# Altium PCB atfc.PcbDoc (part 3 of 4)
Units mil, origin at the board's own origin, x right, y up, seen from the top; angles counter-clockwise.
Board outline 6334.43 x 4147 mil, 6 copper layers (Component Side, Ground Plane (GND), GND/Signal, VCCO/Signal, VCCINT/VCCAUX, Bottom Side), stack 60.473 mil thick; 297 components, 274 nets, 1530 pads, 922 vias.
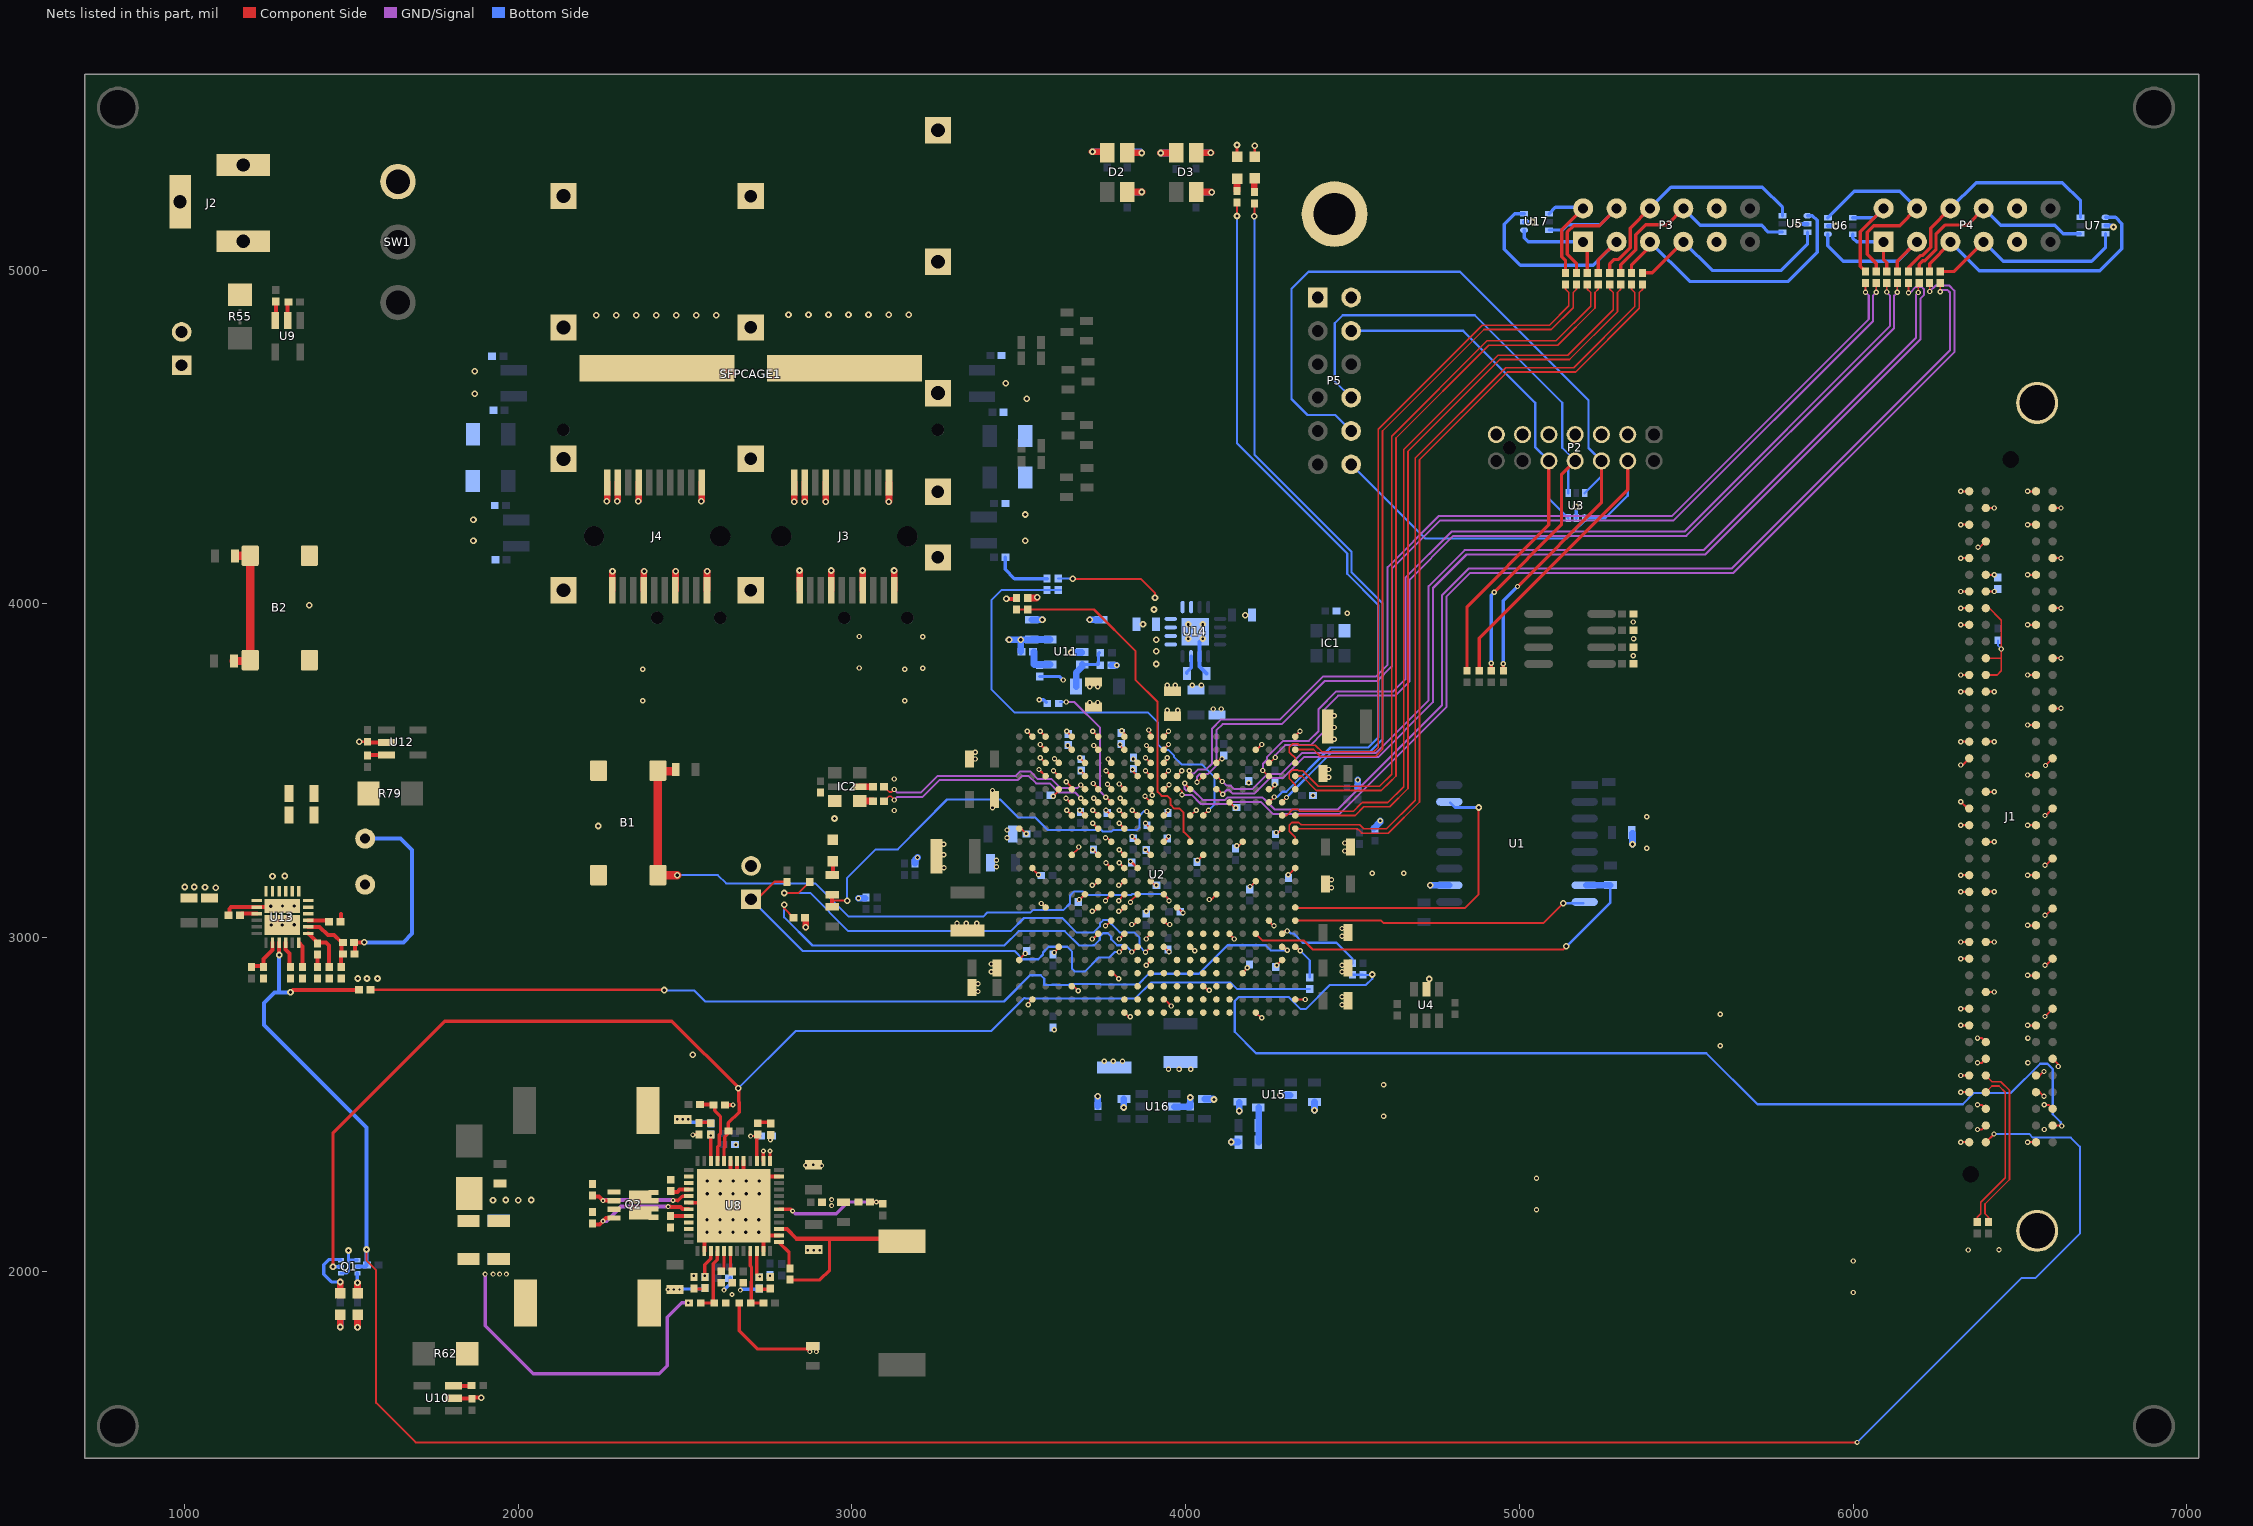
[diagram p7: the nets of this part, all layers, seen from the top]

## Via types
v1: diameter 16, hole 8, Component Side to Bottom Side, tented both sides, 374 vias
v2: diameter 20, hole 10, Component Side to Bottom Side, 243 vias
v3: diameter 16, hole 8, Component Side to Bottom Side, 222 vias
v4: diameter 15, hole 7, Component Side to Bottom Side, 58 vias
v5: diameter 25, hole 10, Component Side to Bottom Side, 20 vias
v6: diameter 19.68, hole 7.87, Component Side to Bottom Side, 4 vias
v7: diameter 20, hole 10, Component Side to Bottom Side, tented both sides, 1 vias

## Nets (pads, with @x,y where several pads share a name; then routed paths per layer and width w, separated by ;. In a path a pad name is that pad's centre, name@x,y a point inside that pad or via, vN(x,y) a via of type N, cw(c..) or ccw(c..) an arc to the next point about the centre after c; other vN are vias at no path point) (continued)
FZ1: U2.AA9 U2.AA10 U2.AA11 U2.AA13 U2.AA14 U2.AA15 U2.AA16 U2.AA17 U2.AB10 U2.AB11 U2.AB12 U2.AB13 U2.AB14 U2.AB15 U2.AB16 U2.AB17 U2.T14 U2.T15 U2.T16 U2.U15 U2.U16 U2.V10 U2.V13 U2.V14 U2.V15 U2.V16 U2.W10 U2.W11 U2.W12 U2.W13 U2.W14 U2.W15 U2.W16 U2.Y10 U2.Y11 U2.Y12 U2.Y13 U2.Y14 U2.Y16 U2.Y17
GBTCLK_N: C4.1 J1.D5 | length 519.3
  Component Side w5: J1.D5@6397.44,2587.2 6415.94,2568.7 6442.39,2568.7 6468.5,2542.59 6468.5,2275.59 6395.01,2202.1 6395.01,2172.45 6405.51,2161.95 C4.1@6405.51,2147.64
GBTCLK_P: C3.1 J1.D4 | length 497.7
  Component Side w5: C3.1@6371.51,2147.64 6371.51,2161.95 6382.01,2172.45 6382.01,2207.48 6455.5,2280.98 6455.5,2537.21 6437.01,2555.7 6415.94,2555.7 J1.D4@6397.44,2537.2
GND: B1.1 B1.2 B2.1 B2.2 C1.1 C2.1 C5.1 C8.1 C9.2 C10.2 C11.2 C12.2 C13.2 C14.2 C15.2 C24.2 C25.2 C26.2 C27.2 C28.2 C29.2 C30.2 C31.2 C32.2 C33.2 C34.2 C35.2 C36.2 C37.2 C38.2 C39.2 C40.2 C41.2 C42.2 C43.2 C44.2 C45.2 C46.2 C47.2 C48.2 C49.1 C50.2 C51.2 C52.2 C53.2 C54.2 C55.2 C56.2 C57.2 C58.2 C59.2 C60.2 C61.2 C62.2 C63.2 C64.2 C65.2 C66.2 C67.2 C68.2 C69.1 C70.1 C71.1 C72.1 C73.1 C74.1 C75.1 C76.1 C77.1 C80.1 C81.1 C82.1 C83.1 C86.1 C88.2 C89.1 C93.1 C95.1 C96.1 C97.1 C98.2 C99.2 C100.2 C101.2 C102.2 C103.2 C107.2 C108.2 C110.2 C111.1 C112.2 C113.2 C114.2 C115.2 C116.2 C117.2 C118.2 C119.1 C120.1 C121.2 C122.1 C123.1 C124.2 C125.1 C126.1 C127.2 C128.1 C129.1 C130.1 Cout1.1 Cout2.1 D1.2 D4.2 D5.2 IC1.3 IC2.3 J1.C1 J1.C4 J1.C5 J1.C8 J1.C9 J1.C12 J1.C13 J1.C16 J1.C17 J1.C20 J1.C21 J1.C24 J1.C25 J1.C28 J1.C29 J1.C32 J1.C33 J1.C34 J1.C36 J1.C38 J1.C40 J1.D2 J1.D3 J1.D6 J1.D7 J1.D10 J1.D13 J1.D16 J1.D19 J1.D22 J1.D25 J1.D28 J1.D35 J1.D37 J1.D39 J1.G1 J1.G4 J1.G5 J1.G8 J1.G11 J1.G14 J1.G17 J1.G20 J1.G23 J1.G26 J1.G29 J1.G32 J1.G35 J1.G38 J1.G40 J1.H3 J1.H6 J1.H9 J1.H12 J1.H15 J1.H18 J1.H21 J1.H24 J1.H27 J1.H30 J1.H33 J1.H36 J1.H39 J2.2 J2.3 J3.1 J3.7 J3.9 J3.10 J3.11 J3.14 J3.17 J3.20 J4.1 J4.7 J4.9 J4.10 J4.11 J4.14 J4.17 J4.20 P1.2 P2.3 P2.5 P2.7 P2.9 P2.11 P2.13 P3.5 P3.11 P4.5 P4.11 P5.1 P5.2 P6.1 pad.2 pad.MH3@6551.18,2121.68 pad.MH3@6551.18,4602 Q1.1 Q1.4 Q2.1 Q2.3 R6.1 R20.1 R24.2 R26.2 R28.2 R30.2 R32.2 R34.2 R48.2 R49.2 R50.2 R51.2 R56.1 R57.1 R58.1 R59.2 R60.1 R63.2 R64.2 R65.1 R67.1 R68.1 R71.1 R73.1 R74.1 R78.1 R82.1 R83.1 Ren2.1 Rf2.1 Rout1.1 Rout2.1 Rout3.1 Rt1.1 SFPCAGE1.1 SFPCAGE1.2 SFPCAGE1.3 SFPCAGE1.4 SFPCAGE1.5 SFPCAGE1.6 SFPCAGE1.7 SFPCAGE1.8 SFPCAGE1.9 SFPCAGE1.10 SFPCAGE1.11 SFPCAGE1.12 SFPCAGE1.13 SFPCAGE1.14 SFPCAGE1.15 SW1.1 U1.10 U2.A2 U2.A3 U2.A5 U2.A7 U2.A9 U2.A11 U2.A12 U2.A22 U2.AA2 U2.AA12 U2.AA22 U2.AB9 U2.AB19 U2.B3 U2.B12 U2.B19 U2.C3 U2.C6 U2.C10 U2.C11 U2.C12 U2.C16 U2.D3 U2.D4 U2.D8 U2.D11 U2.D12 U2.D13 U2.E4 U2.E5 U2.E7 U2.E9 U2.E11 U2.E12 U2.E20 U2.F5 U2.F11 U2.F17 U2.G5 U2.G6 U2.G7 U2.G8 U2.G9 U2.G10 U2.G12 U2.G14 U2.H1 U2.H7 U2.H9 U2.H11 U2.H21 U2.J8 U2.J10 U2.J12 U2.J18 U2.K5 U2.K7 U2.K9 U2.K11 U2.K15 U2.L2 U2.L8 U2.L9 U2.L10 U2.L22 U2.M7 U2.M9 U2.M11 U2.M19 U2.N6 U2.N8 U2.N9 U2.N10 U2.N16 U2.P3 U2.P7 U2.P9 U2.P11 U2.P13 U2.R8 U2.R10 U2.R12 U2.R20 U2.T7 U2.T9 U2.T11 U2.T17 U2.U4 U2.U14 U2.V1 U2.V11 U2.V21 U2.W8 U2.W18 U2.Y5 U2.Y15 U3.2 U4.2 U5.2 U6.2 U7.2 U8.2 U8.11 U8.13 U8.14 U8.17 U8.18 U8.19 U8.30 U8.38 U8.47 U8.49 U9.2 U10.2 U11.2 U12.2 U13.4 U13.4_1 U13.8 U13.9 U13.10 U13.11 U13.12 U13.13 U14.6 U14.17 U15.2 U16.2 U17.2 | length 7405.3
  Component Side w5: U2.E11@3897.09,3444.91 3900,3442 v1(3900,3427) ; U2.E12@3934.69,3444.91 3936.91,3444.91 v1(3950,3458)
  Component Side w6: U2.V1@3501.61,2933.09 3501.61,2934.69 v1(3519.68,2952.76) ; U2.H1@3501.61,3326.8 3506.87,3326.8 v1(3522.64,3311.02) ; v1(3525.24,3618.13) U2.A2@3540.98,3602.39 ; v1(3528,2799.21) 3528,2801.12 3527.56,2801.56 U2.AA2@3540.98,2814.98 ; U2.L2@3540.98,3208.68 3540.98,3207.05 v1(3559.06,3188.98) ; v1(3560.67,3503.96) U2.D3@3580.35,3484.28 ; v1(3564.61,3539.39) U2.C3@3580.35,3523.65 ; v1(3564.61,3578.76) U2.B3@3580.35,3563.02 ; v1(3564.61,3618.13) U2.A3@3580.35,3602.39 ; v1(3566.93,3102.36) 3566.93,3104 U2.P3@3580.35,3090.57 ; v1(3603,3424) 3619.72,3440.72 U2.E4@3619.72,3444.91 ; v1(3603.98,3500.02) U2.D4@3619.72,3484.28 ; v1(3606.3,2955.69) 3606.3,2956.69 U2.U4@3619.72,2970.12 ; v1(3641.72,3417.32) 3653.46,3405.54 U2.F5@3659.09,3405.54 ; v1(3642,3467) 3659.09,3449.91 U2.E5@3659.09,3444.91 ; v1(3643.35,3381.91) U2.G5@3659.09,3366.17 ; v1(3643.35,3618.13) U2.A5@3659.09,3602.39 ; U2.Y5@3659.09,2854.35 3665.33,2854.35 3678,2841.69 v1(3678,2841) ; U2.K5@3659.09,3248.06 3679.61,3268.57 v1(3679.61,3271.61) ; v1@3678,3109.48 U2.N6@3698.46,3129.94 ; v1(3682.72,3381.91) U2.G6@3698.46,3366.17 ; v1(3682.72,3539.39) U2.C6@3698.46,3523.65 ; v1(3720.1,3157.24) 3720.1,3156.42 3722.52,3154 U2.M7@3737.83,3169.31 ; v1(3720.47,2996.06) 3722.06,2996.06 U2.T7@3737.83,3011.83 ; v1(3720.47,3078.73) 3720.47,3076.4 3722.06,3074.8 U2.P7@3737.83,3090.57 ; v1(3722.09,3263.8) U2.K7@3737.83,3248.06 ; v1(3722.09,3342.54) U2.H7@3737.83,3326.8 ; v1(3722.09,3381.91) U2.G7@3737.83,3366.17 ; v1(3722.09,3618.13) U2.A7@3737.83,3602.39 ; v1(3723,3462) 3737.83,3447.17 U2.E7@3737.83,3444.91 ; v1(3759.84,3035.43) 3761.43,3035.43 U2.R8@3777.2,3051.2 ; v1(3759.84,3110.24) 3759.84,3112.58 U2.N8@3777.2,3129.94 ; v1(3759.84,3299.21) 3765.42,3299.21 U2.J8@3777.2,3287.43 ; v1(3761.46,3224.43) U2.L8@3777.2,3208.68 ; v1(3761.46,3381.91) U2.G8@3777.2,3366.17 ; v1(3761.46,3500.02) U2.D8@3777.2,3484.28 ; U2.W8@3777.2,2893.72 3782.86,2893.72 v1(3800,2876.58) ; v1(3799.2,3078.73) 3799.2,3076.4 3800.8,3074.8 U2.P9@3816.57,3090.57 ; v1(3799.21,3110.24) 3799.21,3112.58 U2.N9@3816.57,3129.94 ; v1(3799.2,3157.47) 3799.2,3151.95 U2.M9@3816.57,3169.31 ; v1(3800.8,2996.06) U2.T9@3816.57,3011.83 ; v1(3800.83,3224.43) U2.L9@3816.57,3208.68 ; v1(3800.83,3263.8) U2.K9@3816.57,3248.06 ; v1(3800.83,3342.54) U2.H9@3816.57,3326.8 ; v1(3800.83,3381.91) U2.G9@3816.57,3366.17 ; v1(3800.83,3460.65) U2.E9@3816.57,3444.91 ; v1(3809,3620) 3816.57,3612.43 U2.A9@3816.57,3602.39 ; U2.AB9@3816.57,2775.61 3829.19,2763 v1(3834,2763) ; v1(3834.64,3106.29) 3834.64,3108.64 U2.N10@3855.94,3129.94 ; v1(3834.64,3228.34) 3836.29,3228.34 U2.L10@3855.94,3208.68 ; v1(3838.58,3039.37) 3844.11,3039.37 U2.R10@3855.94,3051.2 ; v1(3840.2,3303.17) U2.J10@3855.94,3287.43 ; v1(3840.2,3381.91) U2.G10@3855.94,3366.17 ; v1(3842.51,3535.43) 3844.16,3535.43 U2.C10@3855.94,3523.65 ; v1(3878,3424) 3877.15,3424 3877,3423.85 U2.F11@3895.32,3405.54 ; v1(3879.57,3263.8) U2.K11@3895.32,3248.06 ; v1(3879.57,3342.54) U2.H11@3895.32,3326.8 ; v1(3879.57,3500.02) U2.D11@3895.32,3484.28 ; v1(3879.57,3539.39) U2.C11@3895.32,3523.65 ; v1(3881.89,2917.32) 3895.32,2930.75 U2.V11@3895.32,2933.09 ; v1(3881.89,2996.06) 3881.89,2998.41 U2.T11@3895.32,3011.83 ; v1(3881.88,3078.73) 3881.88,3077.16 U2.P11@3895.32,3090.57 ; v1(3889.76,3622.11) 3889.76,3618.24 3895.32,3612.68 U2.A11@3895.32,3602.39 ; U2.M11@3895.32,3169.31 3907.63,3157 v1(3912.27,3157) ; U2.AA12@3934.69,2814.98 3936.98,2814.98 v1(3956.69,2795.28) ; U2.R12@3934.69,3051.2 3946.52,3039.37 v1(3952.76,3039.37) ; U2.J12@3934.69,3287.43 3948.82,3301.56 v1(3948.82,3303.15) ; U2.G12@3934.69,3366.17 3949,3380.48 3948.48,3381 v1(3947,3381) ; U2.D12@3934.69,3484.28 3934.69,3485.87 v1(3948.82,3500) ; U2.C12@3934.69,3523.65 3948.82,3537.78 3947.24,3539.36 v1(3944.87,3539.36) ; U2.B12@3934.69,3563.02 3934.69,3564.61 v1(3948.82,3578.74) ; U2.A12@3934.69,3602.39 3934.69,3603.98 v1(3948.82,3618.11) ; U2.P13@3974.06,3090.57 3976.35,3090.57 3991.93,3075 v1(3992.13,3075) ; U2.D13@3974.06,3485.87 U2.D13@3974.06,3484.28 3988.19,3498.41 v1(3988.19,3500) ; U2.U14@4013.43,2972.46 4015.72,2972.46 v1(4027.56,2960.63) ; U2.G14@4013.43,3366.17 4015.77,3366.17 v1(4031.5,3381.89) ; v1(4035.43,3232.28) 4037.02,3232.28 U2.K15@4052.8,3248.06 ; U2.Y15@4052.8,2854.35 4055.09,2854.35 4066.93,2842.52 v1(4070.87,2842.52) ; v1(4070.87,3114.17) 4076.39,3114.17 U2.N16@4092.17,3129.94 ; U2.C16@4092.17,3523.65 4104.52,3536 v1(4109,3536) ; U2.T17@4131.54,3011.83 4131.54,3010.2 v1(4145.67,2996.06) ; U2.F17@4131.54,3405.54 4147.31,3389.76 v1(4149.61,3389.76) ; v1(4153.54,3275.59) 4159.07,3275.59 U2.J18@4170.91,3287.43 ; U2.W18@4170.91,2893.72 4170.91,2895.31 v1(4185.04,2909.45) ; v1(4192.91,3153.54) 4194.5,3153.54 U2.M19@4210.28,3169.31 ; U2.AB19@4210.28,2775.61 4226.05,2759.84 v1(4228.35,2759.84) ; U2.B19@4210.28,3563.02 4212.62,3563.02 v1(4228.35,3578.74) ; U2.R20@4249.65,3051.2 4249.65,3049.57 4263.07,3036.14 v1(4264.49,3036.14) ; U2.E20@4249.65,3444.91 4255.93,3444.91 4267,3455.98 v1(4267,3458) ; v1(4271.65,3314.96) 4277.18,3314.96 U2.H21@4289.02,3326.8 ; v1(4273.24,2917.32) U2.V21@4289.02,2933.09 ; v1(4307.09,3188.98) 4308.68,3188.98 U2.L22@4328.39,3208.68 ; U2.AA22@4328.39,2814.98 v1@4358.24,2814.98 ; U2.A22@4328.39,3602.39 4328.39,3603.98 v1(4342.52,3618.11) ; v3(6322.44,2387.2) J1.C1@6347.44,2387.2 ; v3(6322.44,2537.2) J1.C4@6347.44,2537.2 ; v3(6322.44,2587.2) J1.C5@6347.44,2587.2 ; v3(6322.44,2737.2) J1.C8@6347.44,2737.2 ; v3(6322.44,2787.2) J1.C9@6347.44,2787.2 ; v3(6322.44,2937.2) J1.C12@6347.44,2937.2 ; v3(6322.44,2987.2) J1.C13@6347.44,2987.2 ; v3(6322.44,3137.2) J1.C16@6347.44,3137.2 ; v3(6322.44,3187.2) J1.C17@6347.44,3187.2 ; v3(6322.44,3337.2) J1.C20@6347.44,3337.2 ; v3(6322.44,3407.2) 6342.44,3387.2 J1.C21@6347.44,3387.2 ; v3(6322.44,3517.2) 6327.44,3517.2 J1.C24@6347.44,3537.2 ; v3(6322.44,3587.2) J1.C25@6347.44,3587.2 ; v3(6322.44,3737.2) J1.C28@6347.44,3737.2 ; v3(6322.44,3787.2) J1.C29@6347.44,3787.2 ; v3(6322.44,3937.2) J1.C32@6347.44,3937.2 ; v3(6322.44,3987.2) J1.C33@6347.44,3987.2 ; v3(6322.44,4037.2) J1.C34@6347.44,4037.2 ; v3(6322.44,4137.2) J1.C36@6347.44,4137.2 ; v3(6322.44,4237.2) J1.C38@6347.44,4237.2 ; v3(6322.44,4337.2) J1.C40@6347.44,4337.2 ; v3(6372.44,2425.2) 6385.44,2425.2 J1.D2@6397.44,2437.2 ; v3(6372.44,2499.2) 6385.44,2499.2 J1.D3@6397.44,2487.2 ; v3(6372.44,2625.2) 6385.44,2625.2 J1.D6@6397.44,2637.2 ; v3(6372.44,2699.2) 6385.44,2699.2 J1.D7@6397.44,2687.2 ; v3(6374,4169.28) 6379.52,4169.28 J1.D37@6397.44,4187.2 ; J1.D10@6397.44,2837.2 v3(6422.44,2837.2) ; J1.D13@6397.44,2987.2 v3(6422.44,2987.2) ; J1.D19@6397.44,3287.2 v3(6422.44,3287.2) ; J1.D22@6397.44,3437.2 v3(6422.44,3437.2) ; J1.D25@6397.44,3587.2 v3(6422.44,3587.2) ; J1.D28@6397.44,3737.2 v3(6422.44,3737.2) ; J1.D35@6397.44,4087.2 v3(6422.44,4087.2) ; J1.D39@6397.44,4287.2 v3(6422.44,4287.2) ; J1.D16@6398.03,3137.8 v3(6422.64,3137.8) ; v3(6522.44,2387.2) J1.G1@6547.44,2387.2 ; v3(6522.44,2737.2) J1.G8@6547.44,2737.2 ; v3(6522.44,2887.2) J1.G11@6547.44,2887.2 ; v3(6522.44,3037.2) J1.G14@6547.44,3037.2 ; v3(6522.44,3187.2) J1.G17@6547.44,3187.2 ; v3(6522.44,3337.2) J1.G20@6547.44,3337.2 ; v3(6522.44,3487.2) J1.G23@6547.44,3487.2 ; v3(6522.44,3637.2) J1.G26@6547.44,3637.2 ; v3(6522.44,3787.2) J1.G29@6547.44,3787.2 ; v3(6522.44,3937.2) J1.G32@6547.44,3937.2 ; v3(6522.44,4087.2) J1.G35@6547.44,4087.2 ; v3(6522.44,4237.2) J1.G38@6547.44,4237.2 ; v3(6522.44,4337.2) J1.G40@6547.44,4337.2 ; J1.G4@6547.44,2537.2 6559.44,2537.2 v3(6571.44,2525.2) ; J1.G5@6547.44,2587.2 6559.44,2587.2 v3(6571.44,2599.2) ; v3(6572.44,2499.2) 6585.44,2499.2 J1.H3@6597.44,2487.2 ; v3(6574.8,2763.78) 6574.8,2764.57 J1.H9@6597.44,2787.2 ; v3(6574.8,2917.32) 6577.56,2917.32 J1.H12@6597.44,2937.2 ; v3(6574.8,3066.93) 6577.17,3066.93 J1.H15@6597.44,3087.2 ; v3(6574.8,3216.54) 6576.77,3216.54 J1.H18@6597.44,3237.2 ; v3(6574.8,3366.14) 6576.38,3366.14 J1.H21@6597.44,3387.2 ; v3(6575.98,3515.75) J1.H24@6597.44,3537.2 ; J1.H6@6597.44,2637.2 6614.17,2620.47 v3(6614.17,2614.17) ; J1.H27@6597.44,3687.2 v3(6622.44,3687.2) ; J1.H30@6597.44,3837.2 v3(6622.44,3837.2) ; J1.H33@6597.44,3987.2 v3(6622.44,3987.2) ; J1.H36@6597.44,4137.2 v3(6622.44,4137.2) ; J1.H39@6597.44,4287.2 v3(6622.44,4287.2)
  Component Side w8: v2(1523.62,3586.61) 1548.45,3586.61 Rout3.1@1549,3587.17 ; D5.2@4154,5339 v2(4154,5375) ; D4.2@4207,5340 v2(4207,5373)
  Component Side w10: U8.30@2511.17,2206.13 U8.49@2636.47,2206.13 ; v4@2524.72,2410.55 R65.1@2542.31,2410.55 ; U8.14@2734.9,2331.43 v4(2734.9,2360.88) ; U8.13@2754.58,2331.43 v4(2754.58,2360.88)
  Component Side w12: U9.2@1309.36,4849.7 Rout1.1@1309.36,4904.77 ; C111.1@1470,3045.58 1470,3070.9 ; Rout3.1@1549.68,3584.9 U12.2@1605.76,3584.9 ; U10.2@1807,1620 Rout2.1@1860.07,1620 ; Rout2.1@1861.76,1621.68 v2(1889.68,1621.68) ; U8.38@2557.73,2061.14 U8.49@2557.73,2107.7 ; R68.1@2622.68,2499 v4(2643.66,2499) ; U8.49@2636.47,2206.13 U8.19@2636.47,2331.43 ; U8.49@2656.16,2206.13 U8.18@2656.16,2331.43 ; U8.49@2675.84,2225.81 U8.17@2675.84,2331.43 ; U8.47@2734.9,2061.14 2734.9,2107.7 U8.2@2781.46,2107.7 ; U8.49@2734.9,2284.87 U8.11@2781.46,2284.87
  Component Side w20: v2@2266.66,4309.13 J4.10@2266.66,4363.72 ; J4.11@2282.41,4040.88 v2@2282.41,4097.41 ; v2@2298.16,4309.13 J4.9@2298.16,4363.72 ; v2@2361.15,4309.13 J4.7@2361.15,4363.72 ; J4.14@2376.9,4040.88 v2@2376.9,4097.41 ; J4.17@2471.39,4040.88 v2@2471.39,4097.41 ; v2@2550.13,4309.13 J4.1@2550.13,4363.72 ; J4.20@2565.87,4040.88 v2@2565.87,4097.41 ; v2@2827.68,4306.67 J3.10@2827.68,4363.72 ; J3.11@2843.43,4040.88 v2@2843.43,4099.57 ; v2@2859.18,4306.67 J3.9@2859.18,4363.72 ; R6.1@2859.73,3060 2862.2,3057.53 v2(2862.2,3031.5) ; v2@2922.17,4306.67 J3.7@2922.17,4363.72 ; J3.14@2937.92,4040.88 v2@2937.92,4099.82 ; J3.17@3032.41,4040.88 v2@3032.41,4099.57 ; v2@3111.15,4306.67 J3.1@3111.15,4363.72 ; J3.20@3126.9,4040.88 v2@3126.9,4099.57 ; R32.2@3527,4017.8 v2@3553.23,4017.8
  Bottom Side w8: Q1.4@1469.39,1994.83 1486.96,1994.83 1492.13,2000 1492.13,2035.43 ; v2(1492.13,2062.99) 1492.13,2035.43 ; Q1.1@1518.61,2034.2 1493.35,2034.2 1492.13,2035.43
  Bottom Side w10: v4@2485,1947.32 C77.1@2559.68,1947.32 ; v4(2509.68,2456) 2519,2446.68 C83.1@2577.68,2446.68 ; v4(2616.68,1944) 2635.37,1962.68 R58.1@2635.37,1982 ; v4@2668,1946.32 C86.1@2722.68,1946.32 ; C119.1@3459.73,4140 3459.73,4103.26 3487.2,4075.8 R34.2@3585,4075.8 ; R78.1@3562.99,3782.48 3622.52,3782.48 v1(3633,3772) ; U3.2@5170.59,4257 v2@5170.59,4290.04
  Bottom Side w12: v6(4050.83,3895.14) 4041.98,3886.28 4041.98,3812.67 C107.2@4062.65,3792 ; U17.2@5014,5144.41 v2(5039.59,5144.41) ; v2(5835,5138) 5862.41,5138 U5.2@5863,5138.59 ; U6.2@5924,5132.41 v2(5948.59,5132.41) ; U7.2@6756,5133.59 6775.41,5133.59 v2(6780,5129)
  Bottom Side w20: v1(3019.68,3118.11) R26.2@3039.31,3118.11 ; R30.2@3188.98,3222.52 3188.98,3232.28 v1(3196.85,3240.16) ; C98.2@3539,3952.53 v2@3570.64,3952.53 ; v2(3657.48,3854.33) U11.2@3688.56,3854.33 ; v2(3712.6,3952.76) C130.1@3745.77,3952.76 ; C116.2@3737,2495.73 v2(3737,2525) ; C99.2@3777.73,3816 v3(3794,3816) ; v2(3815,2491) C117.2@3815,2516.53 ; U16.2@3965.5,2493.73 C115.2@4014,2493.73 v2(4014,2521) ; C114.2@4057,2516.53 v2@4083.47,2516.53 ; v2(4137,2388) R83.1@4157.47,2388 ; v2(4161,2481) C113.2@4161,2506.47 ; v2(4283.46,2527.56) U15.2@4312.79,2527.56 ; v2(4386,2483) C112.2@4386,2507.47 ; R28.2@4516,3449.06 v1@4516,3472.19 ; R24.2@4564.02,3327.8 4582.68,3346.46 v1(4582.68,3350.39) ; v2(4733,3157) U1.10@4790,3157 ; v2(5338.58,3279.53) C1.1@5338.58,3312.99
  other v1: 3948.82,2606.3 3980.32,2606.3 4015.75,2606.3 3755.91,2629.92 3783.46,2629.92 3811.02,2629.92 3606.3,2724.41 4468.5,2799.21 4358.27,2814.96 4468.5,2822.83 3377.95,2838.58 3377.95,2862.2 3417.32,2897.64 4468.5,2897.64 4468.5,2917.32 3417.32,2921.26 4468.5,3003.94 4468.5,3027.56 3314.96,3043.31 3342.52,3043.31 3374.02,3043.31 3681.1,3114.17 4437.01,3149.61 4437.01,3173.23 3276.07,3209.57 3433.07,3212.6 3433.07,3232.28 3275.59,3248.03 4476.38,3259.84 3275.59,3279.53 4476.38,3283.46 3464.57,3299.21 3464.57,3322.83 3421.26,3389.76 4381.73,3426 3421.26,3440.94 4188.98,3464.57 4515.75,3472.44 4429.13,3480.32 4429.13,3503.94 3370.08,3535.43 3370.08,3555.12 4444.88,3594.49 4444.88,3629.92 4444.88,3665.35 4082.68,3685.04 4106.3,3685.04 3712.6,3751.97 3736.22,3751.97 3944.88,3755.91 3968.5,3755.91 4019.68,3755.91 4047.24,3755.91 5341,3845 5342,3896 5341,3946 4484.25,3972.44
  other v2: 1925,2213 2000,2213 1963,2214 2039,2214 4085,2515 4730,2876.3 1519.68,2877.95 1547.24,2877.95 1578.74,2877.95 1260,3037.9 1293,3037.9 1329,3038.9 1094,3149.9 1062,3150.9 1001,3151.9 1030,3151.9 1264,3183.9 1301,3184.9 2240.16,3334.65 2948,3357 3872,3939 3570.87,3952.76 4179,3966 1374.02,3996.06 3555.12,4019.68 2283,4098 2377.49,4098 2471.98,4098 2566.46,4098 2843,4100 2938.1,4100 3031.98,4100 3126.46,4100 1866.14,4188.98 3519.68,4188.98 1866.14,4251.97 3519.68,4267.72 5169.29,4291.34 2827.02,4306 2858.51,4306 2921.5,4306 3110.48,4306 2265.54,4308 2297.03,4308 2360.02,4308 2549,4308 3523.62,4614.17 1870.08,4629.92 3460.63,4661.42 1870.08,4696.85 2234,4865 2294,4865 2354,4865 2414,4865 2474,4865 2534,4865 2594,4865 2810,4866 2870,4866 2930,4866 2990,4866 3050,4866 3110,4866 3170,4866
  other v3: 6000,1937.01 6000,2031.5 6344.66,2064.07 6437.01,2064.96 5051.18,2185.04 5051.18,2279.53 6572.44,2425.2 4593,2465 4593,2559.49 6523.44,2625.2 5602,2676.5 6523.44,2699.2 5602,2770.99 4559.06,3192.91 4653.54,3192.91 5381.89,3267.72 5381.89,3362.2 3127,3381 3127,3475.49 2373,3710.01 3158,3710 2373,3804.49 3158,3804.49 3212.6,3807.09 3022,3807.84 3022,3902.33 3212.6,3901.57
  other v4: 2640.68,1931 2665.68,1944 2449.68,1946 2466.68,1946 2483.68,1946 2526.68,1987 2754.68,1987 2867.68,2064 2885.68,2064 2903.68,2064 2939.68,2197 2939.68,2215 2909.68,2317 2861.68,2318 2884.63,2319.69 2652.37,2380 2755.91,2393.7 2523.62,2409.45 2476.68,2456 2493.31,2455.69
  other v5: 2566.18,2117 2604.93,2117 2643.68,2117 2682.43,2117 2721.18,2117 2566.18,2155 2604.93,2155 2643.68,2155 2682.43,2155 2721.18,2155 2567.18,2233 2605.93,2233 2643.68,2233 2683.43,2233 2722.18,2233 2567.18,2271 2605.93,2271 2644.68,2271 2683.68,2271 2722.18,2271
  other v6: 4007.53,3895.14 4007.53,3938.45 4050.83,3938.45
  other v7: 2523.62,2649.61
GTP_CLK_N: C7.2 U2.E6 | length 671.2
  Component Side w5: C7.2@3096.73,3452 3112.23,3436.5 3119.51,3436.5 v3(3127,3443.99)
  Component Side w6: v1(3685.41,3457.59) 3698.09,3444.91 U2.E6@3698.46,3444.91
  GND/Signal w6: v3(3127,3443.99) 3136.25,3434.74 3206.4,3434.74 3256.65,3485 3491.62,3485 3504.62,3498 3534.38,3498 3557.19,3475.19 3598.2,3475.19 3625.4,3448 3675.82,3448 v1(3685.41,3457.59)
GTP_CLK_P: C6.2 U2.F6 | length 675.8
  Component Side w5: C6.2@3096.73,3409 3111.23,3423.5 3117,3423.5 3127,3413.5 v3(3127,3412.5)
  Component Side w6: v1(3685.41,3418.22) 3698.09,3405.54 U2.F6@3698.46,3405.54
  GND/Signal w6: v3(3127,3412.5) 3136.25,3421.74 3211.78,3421.74 3262.04,3472 3497,3472 3510,3485 3529,3485 3551.81,3462.19 3592.82,3462.19 3620.01,3435 3668.63,3435 v1(3685.41,3418.22)
LED0: R42.2 U2.F21 | length 2143.8
  Component Side w6: U2.F21@4289.02,3405.54 4289.02,3406.02 4302,3419 v1(4302,3420)
  Component Side w6.61: v2(4206,5161) R42.2@4206,5199.52
  Bottom Side w6.61: v2(4206,5161) 4206,4446.84 4496.61,4156.22 4496.61,4095.22 4589.61,4002.22 4589.61,3594.42 4552.58,3557.39 4439.27,3557.39 4302,3420.11 v1(4302,3420)
LED1: R43.2 U2.F20 | length 2186
  Component Side w6: U2.F20@4249.65,3405.54 v1(4265.39,3421.28)
  Component Side w6.61: v2(4154,5162) R43.2@4154,5202.72
  Bottom Side w6.61: v2(4154,5162) 4154,4481 4484,4151 4484,4090 4577,3997 4577,3599.65 4547.35,3570 4434.05,3570 4301.36,3437.31 4290.27,3437.31 4274.25,3421.28 v1(4265.39,3421.28)
MGTAVCC1V0: C66.1 C67.1 C68.1 C101.1 R33.2 U2.D6 U2.D10 U2.E8 U2.F7 U2.F9 U14.9 U14.10 U14.11 U14.12 U14.13 U14.14 | length 426.1
  Component Side w6: v2(3662,4075) 3866,4075 3908,4033 v2(3908,4018) ; v1(3685.03,3499.99) 3686.01,3499.99 3698.46,3487.54 U2.D6@3698.46,3484.28 ; v1(3725.15,3418.22) U2.F7@3737.83,3405.54 ; v1(3766,3460) 3777.2,3448.8 U2.E8@3777.2,3444.91 ; v1(3803.89,3418.22) U2.F9@3816.57,3405.54 ; v1(3841,3504) 3841,3499.22 U2.D10@3855.94,3484.28
  Bottom Side w6: R33.2@3618,4075.8 3661.2,4075.8 v2(3662,4075)
  other v1: 3944.88,3681.1 3976.38,3681.1
  other v2: 3912,3820 3912,3858 3912,3893 3905,3983
MGTAVCC1V0_MON: R33.1 R34.1 U2.G15 | length 1434.4
  Component Side w6: U2.G15@4052.8,3366.17 v1(4068.54,3381.91)
  Bottom Side w6: R33.1@3626,4042 3618,4042 3585,4042 3449,4042 3418,4011 3418,3744 3487,3675 3886,3675 3917.32,3643.68 3917.32,3578.68 3934.26,3561.74 3949.08,3561.74 3964.82,3546 3964.82,3541.75 3987.57,3519 4048,3519 4086.61,3480.39 4086.61,3399.98 v1(4068.54,3381.91)
MGTAVTT1V2: C69.2 C70.2 C71.2 C98.1 R31.2 R37.1 R77.2 U2.B5 U2.B7 U2.B9 U2.B11 U2.C4 U2.C8 U11.5 | length 326.3
  Component Side w6: v1(3607.04,3536.33) U2.C4@3619.72,3523.65 ; v1(3646.41,3575.7) U2.B5@3659.09,3563.02 ; v1(3725.15,3575.7) U2.B7@3737.83,3563.02 ; v1(3767.71,3535.43) 3767.71,3533.14 U2.C8@3777.2,3523.65 ; v1(3803.14,3578.73) 3803.14,3576.45 U2.B9@3816.57,3563.02 U2.B9@3816.57,3563.43 ; v1@3883.67,3574.67 U2.B11@3895.32,3563.02
  Component Side w12: v2(3463,4015) 3490.2,4015 R31.2@3493,4017.8 ; U2.B5@3655.49,3564.51 ccw(c3659.09,3568.11) U2.B5@3659.09,3563.02
  Bottom Side w10: v1(3561,3713) 3574.27,3713 R37.1@3582.27,3705
  Bottom Side w20: v2(3471,3893) 3471.31,3892.69 v2(3506.31,3892.69) ; R77.2@3506.31,3857 v2(3506.31,3892.69) ; U11.5@3593.7,3893.47 C98.1@3539,3893.47 3538.21,3892.69 v2(3506.31,3892.69)
  other v1: 3882.63,3575.7 3712.6,3704.72 3736.22,3704.72
MGTAVTT1V2_MON: R31.1 R32.1 U2.J14 | length 1066.7
  Component Side w6: R31.1@3493,3983.27 R32.1@3527,3983.27 3725.39,3983.27 3850.39,3858.27 3850.39,3771.65 3915.84,3706.2 3915.84,3437.1 3927.94,3425 3945,3425 3955.21,3414.79 3955.21,3397.73 3966.25,3386.69 3981.86,3386.69 3994,3374.55 3994,3317.02 4013.43,3297.6 U2.J14@4013.43,3287.43
MODE0: R4.1 U2.U11 | length 1352.8
  Component Side w6: v2(2797,3134) 2840.73,3134 R4.1@2874,3167.27 ; v1(3879.57,2956.72) U2.U11@3895.32,2972.46
  Bottom Side w6: v2(2797,3134) 2875,3134 2989.57,3019.43 3476.13,3019.43 3515.75,3059.06 3629.92,3059.06 3672.83,3016.15 3725.23,3016.15 3742.84,3033.76 3742.84,3042.47 3752.8,3052.43 3766.88,3052.43 3776.84,3042.47 3776.84,3041.53 3802.22,3016.15 3846.06,3016.15 3862.2,3000 3862.2,2974.08 v1(3879.57,2956.72)
MODE1: R6.2 U2.U10 | length 1276
  Component Side w6: v1(3839,2957) 3839,2955.52 3839.74,2956.26 U2.U10@3855.94,2972.46
  Component Side w6.61: v2(2797,3099) 2797,3088.2 R6.2@2825.2,3060
  Bottom Side w6.61: v2(2797,3099) 2797,3061.27 2881.89,2976.38 3456.69,2976.38 3500,3019.68 3637.8,3019.68 3680.54,2976.94 3723.29,2976.94 3723.44,2977.09 3725.97,2977.09 3742.54,2993.65 3742.54,3003.23 3752.67,3013.37 3767.01,3013.37 3777.15,3003.23 3777.15,2995.24 3795.3,2977.09 3819.91,2977.09 3839,2958 v1(3839,2957)
MODE2: P1.1 R5.1 U2.U9 | length 1433.4
  Component Side w6: v1(3801,2957) 3801.11,2957 U2.U9@3816.57,2972.46
  Component Side w6.61: P1.1@2698,3115 2716,3115 2768.27,3167.27 R5.1@2806,3167.27
  Bottom Side w6.61: P1.1@2698,3115 2853.1,2959.9 3487.57,2959.9 3512.02,2935.45 3558.35,2935.45 3572.42,2949.52 3572.42,2955.66 3589.76,2973 3645.11,2973 3659.85,2958.26 3659.85,2907.08 3668.58,2898.35 3697.56,2898.35 3740.16,2940.94 3771.65,2940.94 3787.71,2957 v1(3801,2957)
NetB1_3: B1.3 B1.4 R12.1 U2.N12 | length 2030.9
  Component Side w6: U2.N12@3934.69,3129.94 3950,3114.63 v1(3950,3111)
  Component Side w25: B1.4@2418.58,3500.5 B1.3@2418.58,3187.5 v2(2476.5,3187.5) ; B1.4@2420.08,3499 R12.1@2469.47,3499
  Bottom Side w6: v2(2476.5,3187.5) 2598.5,3187.5 2623,3163 2890,3163 2990.01,3062.99 3393.01,3062.99 3404.82,3074.8 3534.8,3074.8 3543.31,3083.31 3634.49,3083.31 3653.54,3102.36 3653.54,3125.98 3665.35,3137.8 3692.91,3137.8 3702.23,3128.47 3837.14,3128.47 3839.83,3131.17 3933.46,3131.17 3950,3114.63 v1(3950,3111)
NetB2_3: B2.3 B2.4 R15.1 R16.2 | length 404.8
  Component Side w25: R15.1@1148.53,3829 B2.4@1194.91,3829 ; R16.2@1152.02,4144.5 B2.3@1197.42,4144.5 B2.4@1197.42,3831.5
NetC6_1: C6.1 IC2.4 | length 39.2
  Component Side w20: IC2.4@3023.4,3409.68 C6.1@3062.59,3409.68
NetC7_1: C7.1 IC2.5 | length 39.9
  Component Side w20: IC2.5@3023.4,3452 C7.1@3063.27,3452
NetC77_2: C77.2 C78.2 U8.39 | length 82.5
  Component Side w10: C78.2@2559.63,1985.97 2559.63,2020.36 2576.42,2037.15 2576.42,2037.36 2577.42,2038.36 U8.39@2577.42,2061.14
  other v4: 2559.68,1986.69
NetC78_1: C78.1 R60.2 | length 33
  Component Side w10: R60.2@2526.68,1947.31 C78.1@2559.68,1947.31
NetC79_1: C79.1 U8.32 | length 51.6
  Component Side w12: C79.1@2459.53,2166.76 U8.32@2511.17,2166.76
NetC79_2: C79.2 L1.1 Q2.6 Q2.6_1 Q2.6_2 U8.33 U8.34
NetC80_2: C80.2 C81.2 C82.2 L1.2 R61.1 R62.1 | length 995.3
  GND/Signal w10: v4(1901.57,1992.13) 1901.57,1839.89 1900.68,1839 2045.68,1694 2422.68,1694 2446.68,1718 2446.68,1863 2489.68,1906 v4(2509.68,1906)
  other v4: 1925.2,1992.13 1944.88,1992.13 1964.57,1992.13
NetC83_2: C83.2 C84.2 U8.22 | length 76.1
  Component Side w10: U8.22@2577.31,2331.53 C84.2@2577.31,2407.6
  other v4: 2577.68,2407.31
NetC84_1: C84.1 R65.2 | length 35
  Component Side w10: R65.2@2542.31,2446.97 C84.1@2577.31,2446.97
NetC85_1: C85.1 L2.1 Q2.5 Q2.5_1 Q2.5_2 U8.26 U8.27
NetC85_2: C85.2 U8.28 | length 56.5
  Component Side w12: C85.2@2457.68,2238.31 2477,2238.31 2484.18,2245.5 U8.28@2511.17,2245.5
NetC86_2: C86.2 C87.2 U8.46 | length 68
  Component Side w10: C87.2@2715.21,1993.16 U8.46@2715.21,2061.14
  other v4: 2723.68,1985
NetC87_1: C87.1 R67.2 | length 31.7
  Component Side w10: C87.1@2722.68,1946.32 R67.2@2754.35,1946.32
NetC90_1: C90.1 L3.1 U8.3 | length 611.8
  Component Side w10: C90.1@2811.63,1974.55 2903.69,1974.55 2933.07,2003.94 2933.07,2098
  Component Side w12: U8.3@2781.46,2127.39 2805.3,2127.39 2834.68,2098 2933.07,2098 3142.6,2098 L3.1@3150.28,2090.32
NetC90_2: C90.2 U8.1 | length 89.5
  Component Side w10: U8.1@2781.46,2088.02 2811.63,2057.84 C90.2@2811.63,2010.97
NetC91_1: C91.1 C92.1 R70.1 | length 320.7
  Component Side w10: R70.1@2662.58,1905.28 2662.58,1821.67 2716.54,1767.71 2866.15,1767.71 2870.01,1763.85 v4(2874.02,1759.84)
  other v4: 2893.7,1759.84
NetC93_2: C93.2 C94.2 U8.15 | length 131.2
  Component Side w6.61: v4(2696.85,2405.51) 2713.27,2405.51 C94.2@2718.31,2410.55
  Component Side w10: U8.15@2714.68,2331.95 2714.68,2396 2718.31,2399.63 C94.2@2718.31,2407.6
  Bottom Side w6.61: v4(2696.85,2405.51) C93.2@2727.36,2405.51
NetC94_1: C94.1 R71.2 | length 37
  Component Side w10: C94.1@2718.31,2446.97 R71.2@2755.31,2446.97
NetC96_2: C96.2 U8.42 | length 53.5
  Component Side w10: C96.2@2636.47,2007.9 2636.18,2008.19 2636.18,2060.85 U8.42@2636.47,2061.14
NetC99_1: C99.1 D8.2 R76.1 U11.3 | length 159.2
  Bottom Side w10: U11.3@3690.23,3818.6 3738.72,3818.6 3738.72,3851.4 R76.1@3741.32,3854
  Bottom Side w20: D8.2@3671.85,3751.97 3671.85,3793.9 3690.23,3812.28 U11.3@3690.23,3818.6
NetC105_1: C105.1 L4.1 U13.5 U13.6 U13.7 U13.14 U13.14_1 | length 169.7
  Component Side w12: C105.1@1135.32,3073.9 1135.32,3086.21 1140.53,3091.43 U13.14@1217.14,3091.43 1259,3091.43 U13.14_1@1290.53,3091.43
  other v2: 1259,3093.9 1294,3094.9 1329,3094.9
NetC105_2: C105.2 U13.15 | length 45.5
  Component Side w12: C105.2@1171.69,3071.74 U13.15@1217.14,3071.74
NetC106_1: C106.1 Cout1.2 Cout2.2 L4.2 R79.1 Rf1.2 | length 621.1
  Component Side w12: Rf1.2@1511.69,2950.9 1511.69,2985.9 v2(1539,2985.9)
  Bottom Side w12: v2(1539,2985.9) 1656,2985.9 1682,3011.9 1682,3262.9 1648.1,3296.8 L4.2@1542,3296.8
NetC106_2: C106.2 Rf1.1 Rf2.2 U13.2 | length 190.1
  Component Side w12: U13.2@1370.86,3032.37 1405.38,3032.37 1429.85,3007.9 1448.91,3007.9 1470.47,2986.34 1470.47,2985.9 1470.47,2950.9 Rf1.1@1470.47,2948.9 ; Rf2.2@1470,2914.58 Rf1.1@1470,2948.58
NetC107_1: C107.1 U14.7 | length 56.3
  Bottom Side w10: C107.1@4003.59,3792 4003.59,3795.47 4016.39,3808.27 U14.7@4016.39,3842.98
NetC108_1: C108.1 U13.24 | length 74.9
  Component Side w12: U13.24@1343.21,2985.03 1354,2974.25 C108.1@1354,2914.58
NetC109_1: C109.1 C110.1 U13.1 | length 139.7
  Component Side w12: U13.1@1370.86,3012.68 1371.9,3012.68 1399,2985.58 1424.32,2985.58 1434,2975.9 C110.1@1434,2914.58
NetC109_2: C109.2 R82.2 | length 31.6
  Component Side w12: R82.2@1399,2914.58 C109.2@1399,2946.21
NetC111_2: C111.2 U13.3 | length 61.9
  Component Side w12: U13.3@1370.86,3052.06 1426.84,3052.06 C111.2@1431,3047.9
NetD1_1: D1.1 R8.1 | length 39
  Component Side w12: R8.1@2943,3189.53 D1.1@2943,3228.52
NetD2_2: D2.2 R38.1 | length 87.5
  Component Side w20: v2@3718.53,5355 v2(3721,5355) D2.2@3762.53,5355
  Bottom Side w20: v2(3721,5355) 3764.53,5355
NetD2_3: D2.3 R39.1 | length 83.5
  Component Side w20: D2.3@3824.53,5352.06 3868,5352.06 v2@3868.53,5352.06
  Bottom Side w20: 3825,5354.53 v2@3864.47,5354.53
  other v2: 3868,5351
NetD2_4: D2.4 R44.2 | length 87.5
  Component Side w20: D2.4@3824.53,5233.94 3868,5233.94 v2@3869.53,5233.94
  Bottom Side w20: R44.2@3825,5233.53 v2@3867.53,5233.53
  other v2: 3868,5234
NetD3_2: D3.2 R40.1 | length 93.4
  Component Side w20: v2@3924.53,5351 v2(3925,5351) D3.2@3971.42,5351
  Bottom Side w20: v2(3925,5351) 3971.53,5351
NetD3_3: D3.3 R41.1 | length 88.4
  Component Side w20: D3.3@4031.53,5352.06 4075,5352.06 v2@4076.42,5352.06
  Bottom Side w20: 4031,5351.53 v2@4074.53,5351.53
  other v2: 4075,5352
NetD3_4: D3.4 R45.2 | length 91.4
  Component Side w20: D3.4@4031.53,5233.94 v2@4076.42,5233.94
  Bottom Side w20: R45.2@4031,5233.53 v2@4077.47,5233.53
  other v2: 4078,5233
NetD4_1: D4.1 R42.1 | length 40
  Component Side w20: R42.1@4206,5234.05 D4.1@4206,5274.04
NetD5_1: D5.1 R43.1 | length 36.8
  Component Side w20: R43.1@4154,5237.25 D5.1@4154,5274.04
NetD6_1: D6.1 R46.1 | length 72.3
  Component Side w20: v2(1467,1833.52) D6.1@1467,1870.04
  Bottom Side w20: v2(1467,1833.52) R46.1@1467,1869.25
NetD6_2: D6.2 Q1.6 | length 180.1
  Component Side w20: D6.2@1467,1935 v2(1467,1968.52)
  Bottom Side w10: v2(1467,1968.52) 1440.93,1968.52 1417.32,1992.13 1417.32,2019.68 1433.66,2036.02 1467.58,2036.02 Q1.6@1469.39,2034.2
NetD7_1: D7.1 R47.1 | length 75.3
  Component Side w20: v2(1519,1832.52) D7.1@1519,1870.04
  Bottom Side w20: v2(1519,1832.52) R47.1@1519,1870.25
NetD7_2: D7.2 Q1.3 | length 59.4
  Component Side w20: D7.2@1519,1935 v2(1519,1966.52)
  Bottom Side w10: v2@1518.61,1966.91 Q1.3@1518.61,1994.83
NetJ1_D29: J1.D29 J1.D30 J1.D33 R19.1 | length 356
  Component Side w5: J1.D29@6397.44,3787.2 6431.2,3787.2 6444,3800 6444,3837.2 ; J1.D30@6397.44,3837.2 6444,3837.2 ; J1.D33@6397.44,3987.2 6397.44,3997.56 6402.62,3992.38 6444,3951 v3(6444,3865) 6444,3837.2
  Bottom Side w5: R19.1@6434,3891.27 6434,3875 v3(6444,3865)
NetJ1_D34: J1.D34 R20.2 | length 25
  Component Side w5: J1.D34@6397.44,4037.2 v3(6422.44,4037.2)
NetJ2_1: J2.1 P6.2 R55.1
NetP2_4: P2.4 P5.12 R9.2 U3.1 | length 1896.3
  Component Side w10: R9.2@4879.33,3799.8 4879.33,3897.33 5324.48,4342.48 P2.4@5324.48,4428.63
  Bottom Side w6.89: P5.12@4496,4418 4718,4196 5142,4196 5181.74,4235.74 5182.77,4235.74 5195,4247.97 U3.1@5195,4257 5257,4257 5324.48,4324.48 P2.4@5324.48,4428.63
NetP2_6: P2.6 P5.10 R10.2 U3.6 | length 2686.1
  Component Side w10: R10.2@4952,3799.8 v3(4952,3821) ; v3@4994,4051 4994.5,4051.5 5245.74,4302.74 P2.6@5245.74,4428.63
  Bottom Side w6.89: P5.10@4496,4518 4448,4566 4365,4566 4317,4614 4317,4944 4368,4995 4822,4995 5207,4610 5207,4467.37 P2.6@5245.74,4428.63 5245.74,4382.54 U3.6@5195,4331.8
  Bottom Side w10: v3(4952,3821) 4952,4010 v3(4994,4052)
NetP2_8: P2.8 P5.8 R11.2 U3.4 | length 2073.5
  Component Side w10: R11.2@4915.67,3799.8 v3(4915.67,3822.33) ; v3@4923,4034 4924.5,4035.5 5125.98,4236.98 5125.98,4387.61 P2.8@5167,4428.63
  Bottom Side w6.89: P5.8@4496,4618 4447,4667 4447,4841 4471,4865 4866,4865 5128,4603 5128,4467.63 P2.8@5167,4428.63 5146.18,4407.81 U3.4@5146.18,4331.8
  Bottom Side w10: v3(4915.67,3822.33) 4915.67,4025.67 v3(4925,4035)
NetP2_10: P2.10 P5.4 R14.2 U3.3 | length 1757.6
  Component Side w10: R14.2@4843,3799.8 4843,3992 5088.26,4237.26 P2.10@5088.26,4428.63
  Bottom Side w6.89: P5.4@4496,4818 4832,4818 5047,4603 5047,4469.89 P2.10@5088.26,4428.63 5088.26,4314.92 U3.3@5146.18,4257
NetP3_1: P3.1 R80.2 U17.1 | length 301.4
  Component Side w10: P3.1@5187.71,5081.71 5203.29,5066.14 R80.2@5203.29,4991.73
  Bottom Side w10: U17.1@5014,5120 5014,5097 5026,5085 P3.1@5191,5085
NetP3_2: P3.2 R98.2 U17.3 | length 647.5
  Component Side w10: R98.2@5236.43,4991.73 5236.43,5030.43 P3.2@5291,5085
  Bottom Side w10: U17.3@5014,5168.82 4985.82,5168.82 4955,5138 4955,5063 5003,5015 5221,5015 P3.2@5291,5085
NetP3_3: P3.3 R100.2 U5.1 | length 832.6
  Component Side w10: R100.2@5335.86,4991.73 5335.86,5015.86 5390.57,5070.57 P3.3@5390.57,5084.57
  Bottom Side w10: P3.3@5391,5085 5510,4966 5805,4966 5892,5053 5892,5149 5878,5163 U5.1@5863,5163
NetP3_4: P3.4 R102.2 U5.3 | length 638.6
  Component Side w10: R102.2@5369,4991.73 5397.73,4991.73 P3.4@5491,5085 P3.4@5492,5084
  Bottom Side w10: P3.4@5491,5085 5577,4999 5784,4999 5863,5078 U5.3@5863,5114.18
NetP3_7: P3.7 R97.1 U17.4 | length 335.7
  Component Side w10: R97.1@5138,4991.73 5138,5029.37 5127,5040.37 5127,5121 P3.7@5191,5185
  Bottom Side w10: U17.4@5088.8,5168.82 5108,5188.02 5187.98,5188.02 P3.7@5191,5185
NetP3_8: P3.8 R99.1 U17.6 | length 540.7
  Component Side w10: R99.1@5171.14,4991.73 5171.14,5018.86 5143,5047 5143,5114.37 5162.06,5133.43 5239.43,5133.43 P3.8@5291,5185
  Bottom Side w10: U17.6@5088.8,5120 5129,5120 5145,5136 5242,5136 P3.8@5291,5185
NetP3_9: P3.9 R101.1 U5.6 | length 723.8
  Component Side w10: R101.1@5270.57,4991.73 5270.57,5018.57 5284,5032 5297,5032 5332,5067 5332,5126 P3.9@5391,5185
  Bottom Side w10: P3.9@5391,5185 5454,5248 5728,5248 5788.2,5187.8 U5.6@5788.2,5163
NetP3_10: P3.10 R103.1 U5.4 | length 634.9
  Component Side w10: R103.1@5303.71,4991.73 5303.71,5016.09 5348,5060.37 5348,5106 5378.29,5136.29 5442.29,5136.29 P3.10@5491,5185
  Bottom Side w10: P3.10@5491,5185 5542,5134 5726,5134 5745.82,5114.18 U5.4@5788.2,5114.18
NetP4_1: P4.1 R104.2 U6.6 | length 207.4
  Component Side w10: P4.1@6087,5081 P4.1@6091,5085 6091,5031 6100.29,5021.71 R104.2@6100.29,4995.73
  Bottom Side w10: U6.6@5998.8,5108 5998.8,5096.2 6010,5085 P4.1@6091,5085
NetP4_2: P4.2 R106.2 U6.1 | length 458.6
  Component Side w10: R106.2@6132.43,4995.73 6132.43,5026.43 P4.2@6191,5085
  Bottom Side w10: U6.1@5924,5108 5924,5073 5970,5027 6133,5027 P4.2@6191,5085
NetP4_3: P4.3 R108.2 U7.1 | length 822.4
  Component Side w10: R108.2@6228.86,4995.73 6228.86,5019.62 P4.3@6291,5081.76 ; P4.3@6291,5085 P4.3@6292,5084
  Bottom Side w10: P4.3@6291,5085 6378,4998 6739,4998 6805,5064 6805,5139 6786,5158 U7.1@6756,5158
NetP4_4: P4.4 R110.2 U7.3 | length 617.8
  Component Side w10: R110.2@6261,4995.73 6301.73,4995.73 P4.4@6391,5085 P4.4@6394,5082
  Bottom Side w10: P4.4@6391,5085 6449,5027 6714,5027 6756,5069 U7.3@6756,5109.18
NetP4_7: P4.7 R105.1 U6.4 | length 328.8
  Component Side w10: R105.1@6037,4995.73 6021,5011.73 6021,5115 P4.7@6091,5185
  Bottom Side w10: U6.4@5998.8,5156.82 6062.82,5156.82 P4.7@6091,5185
NetP4_8: P4.8 R107.1 U6.3 | length 628.5
  Component Side w10: R107.1@6069.14,4995.73 6069.14,5019.86 6042,5047 6042,5113.37 6061.63,5133 6139,5133 P4.8@6191,5185
  Bottom Side w10: U6.3@5924,5156.82 6003.18,5236 6140,5236 P4.8@6191,5185
NetP4_9: P4.9 R109.1 U7.6 | length 739.1
  Component Side w10: R109.1@6165.57,4995.73 6165.57,5007.57 6202,5044 6207.98,5044 6232,5068.02 6232,5126 P4.9@6291,5185
  Bottom Side w10: P4.9@6291,5185 6368,5262 6627,5262 6681.2,5207.8 U7.6@6681.2,5158
NetP4_10: P4.10 R111.1 U7.4 | length 633.1
  Component Side w10: R111.1@6197.71,4995.73 6197.71,5017.09 6208.63,5028 6214.61,5028 6248,5061.39 6248,5108 6275,5135 6341,5135 P4.10@6391,5185
  Bottom Side w10: P4.10@6391,5185 6442,5134 6604,5134 6628.82,5109.18 U7.4@6681.2,5109.18
NetQ2_2: Q2.2 R64.1 U8.29 | length 332.5
  Component Side w10: v4(2464.1,2213) 2477.69,2213 2478.68,2212 2492.5,2225.81 U8.29@2511.17,2225.81
  Component Side w12: R64.1@2223.31,2224.6 2242.09,2224.6 v4(2254.41,2212.28) Q2.2@2287.82,2212.28
  GND/Signal w12: v4(2254.41,2212.28) 2255.63,2213.5 v4@2463.6,2213.5
NetQ2_4: Q2.4 R63.1 U8.31 | length 350.9
  Component Side w12: R63.1@2223.31,2140.6 2244.28,2140.6 v4(2254.14,2150.45) 2263.99,2160.31 Q2.4@2287.82,2160.31 ; v4(2449.68,2194) 2455.52,2194 2456.02,2193.5 2486.06,2193.5 2493.12,2186.44 U8.31@2511.17,2186.44
  GND/Signal w12: v4(2254.14,2150.45) 2265.14,2150.45 2308.68,2194 v4(2449.68,2194)
NetR1_1: R1.1 R8.2 U2.G11 | length 1244
  Component Side w6: 2945,3111 v2(2986,3111) ; v1(3883,3378) 3883,3378.48 3883.24,3378.24 U2.G11@3895.32,3366.17 U2.G11@3895.32,3366.68
  Component Side w12: R1.1@2941,3092.53 R8.2@2941,3128.47
  Bottom Side w6: v2(2986,3111) 2986,3178.91 3071.91,3264.83 3137.8,3264.83 3285,3414 3444,3414 3498,3360 3550,3360 3587.52,3322.48 3614.08,3322.48 3614.44,3322.83 3670.07,3322.83 3670.45,3322.46 3699.55,3322.46 3699.93,3322.83 3747.07,3322.83 3750.45,3319.46 ; 3751.54,3318.36 3778.46,3318.36 3782.93,3322.83 3835.86,3322.83 3836.22,3322.48 3853.48,3322.48 3862.2,3331.2 3862.2,3366.14 3876.06,3380 3878.06,3378 v1(3883,3378)
NetR13_1: R13.1 U2.U12 | length 21.3
  Component Side w6: U2.U12@3934.69,2972.46 3949.15,2958 v1(3950,2958)
NetR37_2: R37.2 U2.F8 | length 390.8
  Component Side w6: v1(3761,3421) 3761.74,3421 U2.F8@3777.2,3405.54
  GND/Signal w6: v1@3642,3705 v1(3642,3706) 3667,3706 3744.09,3628.91 3744.09,3437.91 v1(3761,3421)
  Bottom Side w6: R37.2@3623.8,3706 v1(3642,3706)
NetR59_1: R59.1 R61.2 U8.40 | length 196.7
  Component Side w10: R61.2@2549,1905.28 2584.63,1905.28 2584.63,2022.73 2592.42,2030.52 2592.42,2030.73 2597.1,2035.42 U8.40@2597.1,2061.14
NetR66_1: R66.1 R68.2 U8.21 | length 216.1
  Component Side w10: R68.2@2588.68,2493.63 2588.68,2482 2606.3,2464.39 2606.3,2413.24 2602.68,2409.63 2602.68,2378.41 2597.68,2373.41 U8.21@2597.68,2332.01
  Component Side w12: R66.1@2547.68,2500 2582.31,2500 R68.2@2588.68,2493.63
NetR69_1: R69.1 R70.2 U8.45 | length 196.1
  Component Side w10: U8.45@2695.53,2061.14 2695.53,2043.22 2695.66,2043.09 2695.66,2027.77 2695.53,2027.63 2695.53,2017.08 2699.21,2013.4 2699.21,1969.85 2699,1969.64 2699,1962.36 2698.91,1962.27 2698.91,1930.36 2699,1930.27 R70.2@2699,1905.28 ; R70.2@2697.11,1905.28 R70.2@2699,1905.28 ; R69.1@2735.58,1905.28 R70.2@2699,1905.28
NetR72_1: R72.1 R73.2 U8.6 | length 349.2
  Component Side w10: U8.6@2781.46,2186.44 2817.49,2186.44 v4(2822.83,2181.1) ; R73.2@3056.37,2208 v4(3073.37,2208) 3090.37,2208 R72.1@3092.68,2205.68
  GND/Signal w10: v4(2822.83,2181.1) 2830.65,2173.23 2952.76,2173.23 2987.53,2208 v4(3073.37,2208)
NetR74_2: R74.2 U8.41 | length 51.4
  Component Side w10: R74.2@2616.79,2009.79 U8.41@2616.79,2061.14
NetR77_1: R77.1 R78.2 U11.4 | length 86.3
  Bottom Side w20: R77.1@3545.68,3857 3545.68,3819 3546.09,3818.6 3562.99,3818.6 U11.4@3593.77,3818.6
NetR81_1: R81.1 R83.2 U15.4 | length 104.7
  Bottom Side w20: R83.2@4218.53,2387 4218.53,2437 4218.77,2437.24 U15.4@4218.77,2491.6
NetRen1_2: Ren1.2 Ren2.2 U13.20 | length 117.8
  Component Side w12: Ren1.2@1201,2914.58 1237,2914.58 1237,2935.9 1264.47,2963.37 U13.20@1264.47,2985.03
NetRin1_2: Rin1.2 U9.3 | length 53.7
  Component Side w12: U9.3@1274.05,4850.42 Rin1.2@1274.05,4904.09
NetRin2_2: Rin2.2 U10.3 | length 51.5
  Component Side w12: U10.3@1807,1657.4 Rin2.2@1858.47,1657.4
NetRin3_2: Rin3.2 U12.3 | length 52.5
  Component Side w12: Rin3.2@1553.28,3547.5 U12.3@1605.76,3547.5
NetRt1_2: Rt1.2 U13.22 | length 75.1
  Component Side w12: U13.22@1303.84,2985.03 1303.84,2964.06 1315,2952.9 Rt1.2@1315,2914.58
PGOOD: Q1.5 R21.2 R75.1 U8.20 | length 3950.9
  Component Side w10: v2(1445.48,2014.52) 1445.48,2415.48 1780,2750 2461,2750 2661.16,2549.84 2661.16,2507.66 2662.16,2506.66 2662.16,2477.12 2629.95,2444.91 R75.1@2629.95,2421 ; U8.20@2616.79,2331.43 2616.79,2369.89 2618.68,2371.79 2618.68,2403 2627,2411.32 R75.1@2627,2421
  Bottom Side w6: v2(2660,2549) 2831.47,2720.47 3417.32,2720.47 3515.75,2818.9 3519.25,2818.9 3520.15,2818 3849.5,2818 3897.64,2866.14 4133.86,2866.14 4154.06,2845.94 R21.2@4372,2845.94
  Bottom Side w10: v2(1445.48,2014.52) Q1.5@1469.39,2014.52
PGOOD_R: R21.1 U2.U22 | length 111.9
  Component Side w6: U2.U22@4328.39,2972.46 4331.54,2972.46 v1(4343,2961)
  Bottom Side w6.61: v1(4343,2961) 4372,2932 R21.1@4372,2880.46
PGOOD_VADJ: J1.D1 Q1.2 R17.1 R22.2 U13.21 | length 7873.4
  Component Side w6: v2(1546,2066) 1546,2032.74 1574.8,2003.94 1574.8,1606.3 1693.1,1488 v4(6011.81,1488) ; J1.D1@6397.44,2387.2 6422,2411.76 v3(6422,2412)
  Component Side w12: v2@1284.16,2949.74 U13.21@1284.16,2985.03 ; v2@1325.2,2844 R22.2@1523.2,2844
  Bottom Side w6: v4(6011.81,1488) 6503.81,1980 6546,1980 6679,2113 6679,2374 6652,2401 6538,2401 6527,2412 v3@6429,2412
  Bottom Side w8: v2(1546,2066) 1547.27,2064.73 R17.1@1547.27,2019
  Bottom Side w12: v2(1284,2948) 1284,2835.73 ; v2(1318.2,2837) 1316.94,2835.73 1284,2835.73 ; Q1.2@1518.61,2014.52 1542.52,2014.52 1546,2018 1546,2019 v2(1546,2066) 1546,2431 1239,2738 1239,2804 1270.73,2835.73 1284,2835.73
PGOOD_VADJ_R: R22.1 U2.U21 | length 2892.3
  Component Side w6: U2.U21@4289.02,2972.46 4293.54,2972.46 v1(4304,2962)
  Component Side w6.61: R22.1@1557.73,2844 v2@2438,2844
  Bottom Side w6: 3737.47,2860.95 3745.01,2860.95 3746.38,2859.58 3857.28,2859.58 3889.84,2892.14
  Bottom Side w6.61: v2@2439,2842 2528,2842 2561,2809 3455.52,2809 3533.91,2887.39 3566.22,2887.39 3576.36,2877.25 3576.36,2862.91 3575.55,2862.09 3575.55,2858.27 3599.16,2858.27 3599.87,2858.98 3614.21,2858.98 3614.92,2858.27 3650.46,2858.27 3653.14,2860.95 3737.47,2860.95 ; 3889.84,2892.14 4040.14,2892.14 4125.15,2977.15 4239.85,2977.15 4255,2962 v1(4304,2962)
  other v2: 2438,2843
PMODA1_N: R98.1 U2.D22 | length 2182.5
  Component Side w5: U2.D22@4328.39,3484.28 4348.34,3484.28 4391.62,3441 4586.38,3441 4611.38,3466 4630,3484.62 4630,4497 4908,4775 5114.74,4775 5226.36,4886.62 5226.36,4932.82 5236.43,4942.89 R98.1@5236.43,4957.2
PMODA1_P: R80.1 U2.E22 | length 2240.6
  Component Side w5: U2.E22@4328.39,3444.91 4328.39,3458.34 4310.04,3476.68 4310.04,3492.04 4318.14,3500.14 4318.31,3500.14 4320.79,3502.62 4335.98,3502.62 4338.46,3500.14 4350.86,3500.14 4397,3454 4581,3454 4617,3490 4617,4502.38 4902.62,4788 5109.36,4788 5213.36,4892 5213.36,4932.82 5203.29,4942.89 R80.1@5203.29,4957.2
PMODA2_N: R102.1 U2.H22 | length 2363.7
  Component Side w5: U2.H22@4328.39,3326.8 4514.2,3326.8 4524,3317 4527.81,3313.19 4607.19,3313.19 4611,3317 4700.5,3406.5 4700.5,4431.5 4964,4695 5168.31,4695 5358.93,4885.62 5358.93,4932.82 5369,4942.89 R102.1@5369,4957.2
PMODA2_P: R100.1 U2.J22 | length 2423.3
  Component Side w5: U2.J22@4328.39,3287.43 4328.39,3300.86 4310.04,3319.2 4310.04,3337.04 4318.14,3345.14 4338.86,3345.14 4346,3338 4521.38,3338 4533.19,3326.19 4601.81,3326.19 4687.5,3411.88 4687.5,4436.88 4958.62,4708 5162.93,4708 5345.93,4891 5345.93,4932.82 5335.86,4942.89 R100.1@5335.86,4957.2
PMODA3_N: R99.2 U2.B22 | length 2030.2
  Component Side w5: U2.B22@4328.39,3563.02 4329.38,3564.01 4383,3564.01 4403.01,3544 4569.38,3544 4590,3564.62 4590,4518 4894,4822 5095.46,4822 5161.07,4887.62 5161.07,4932.82 5171.14,4942.89 R99.2@5171.14,4957.2
PMODA3_P: R97.2 U2.C22 | length 2088.3
  Component Side w5: U2.C22@4328.39,3523.65 4328.39,3538.61 4322.33,3544.67 4320.79,3544.67 4310.04,3555.42 4310.04,3570.61 4320.79,3581.36 4335.98,3581.36 4340.33,3577.01 4388.38,3577.01 4408.39,3557 4564,3557 4577,3570 4577,4523.38 4888.62,4835 5090.07,4835 5148.07,4893 5148.07,4932.82 5138,4942.89 R97.2@5138,4957.2
PMODA4_N: R103.2 U2.G22 | length 2267.9
  Component Side w5: U2.G22@4328.39,3366.17 4508.17,3366.17 4534,3392 4611,3392 4666,3447 4666,4457 4941,4732 5150.03,4732 5293.64,4875.62 5293.64,4932.82 5303.71,4942.89 R103.2@5303.71,4957.2
PMODA4_P: R101.2 U2.G21 | length 2295.5
  Component Side w5: U2.G21@4289.02,3366.17 4302.45,3366.17 4320.79,3384.51 4335.98,3384.51 4341.33,3379.17 4502.78,3379.17 4524.81,3401.19 4528.62,3405 4605.62,3405 4653,3452.38 4653,4462.38 4935.62,4745 5144.64,4745 5280.64,4881 5280.64,4932.82 5270.57,4942.89 R101.2@5270.57,4957.2
PMODB1_N: R106.1 U2.C20 | length 2772.2
  Component Side w5: U2.C20@4249.65,3523.65 4251.65,3523.65 v1(4268,3540) ; v3(6132.43,4933.43) R106.1@6132.43,4961.2
  GND/Signal w6: v1(4268,3540) 4268,3547 4298,3577 4374.38,3577 4411,3613.62 4411,3679 4457,3725 4627.38,3725 4671,3768.62 4671,4073 4802,4204 5500.24,4204 6122.86,4826.62 6122.86,4923.86 v3(6132.43,4933.43)
PMODB1_P: R104.1 U2.D20 | length 2821.6
  Component Side w5: v1(4231,3501) 4247.72,3484.28 U2.D20@4249.65,3484.28 ; v3(6100.29,4934.29) R104.1@6100.29,4961.2
  GND/Signal w6: v1(4231,3501) 4231,3520.33 4243.02,3532.35 4243.02,3540.41 4292.62,3590 4369,3590 4398,3619 4398,3684.38 4451.62,3738 4622,3738 4658,3774 4658,4078.38 4796.62,4217 5494.86,4217 6109.86,4832 6109.86,4924.71 v3(6100.29,4934.29)
PMODB2_N: R110.1 U2.E14 | length 3363.7
  Component Side w5: v1(3997,3463) 3997,3461.33 U2.E14@4013.43,3444.91 ; v3(6261,4935) R110.1@6261,4961.2
  GND/Signal w6: v1(3997,3463) 3997,3446 4002,3441 4023.38,3441 4051.38,3413 4118.04,3413 4124.81,3419.76 4230.62,3419.76 4236.27,3414.12 4266.38,3384 4456,3384 4768,3696 4768,4026.38 4847.62,4106 5636,4106 6290,4760 6290,4933 6282,4941 6267,4941 v3(6261,4935)
PMODB2_P: R108.1 U2.E13 | length 3434.8
  Component Side w5: U2.E13@3974.06,3444.91 3982.09,3444.91 3989,3438 v1(3989,3428) ; R108.1@6228.86,4961.2 6229,4961.06 v3(6229,4936)
  GND/Signal w6: v1(3989,3428) 4018,3428 4046,3400 4123.43,3400 4130.19,3406.76 4225.24,3406.76 4261,3371 4461.38,3371 4781,3690.62 4781,4021 4853,4093 5641.38,4093 6303,4754.62 6303,4938.38 6287.38,4954 6246.71,4954 6229,4936.29 v3(6229,4936)
PMODB3_N: R107.2 U2.D15 | length 2984.9
  Component Side w5: v1(4034,3465.48) U2.D15@4052.8,3484.28 ; v3(6069.14,4934.14) R107.2@6069.14,4961.2
  GND/Signal w6: v1(4034,3465.48) 4034,3482 4043,3491 4067.38,3491 4092,3515.62 4092,3621 4111,3640 4287.38,3640 4416.38,3769 4574.38,3769 4618,3812.62 4618,4105 4763,4250 5461.96,4250 6059.57,4847.62 6059.57,4924.57 v3(6069.14,4934.14)
PMODB3_P: R105.2 U2.D14 | length 2964.7
  Component Side w5: v1(4011.11,3499.8) 4011.11,3486.74 4013.43,3484.43 U2.D14@4013.43,3484.28 ; v3(6037,4934) R105.2@6037,4961.2
  GND/Signal w6: v1(4011.11,3499.8) 4019.68,3491.23 4024.85,3491.23 4037.62,3504 4062,3504 4079,3521 4079,3626.38 4105.62,3653 4282,3653 4411,3782 4569,3782 4605,3818 4605,4110.38 4757.62,4263 5456.57,4263 6046.57,4853 6046.57,4924.43 v3(6037,4934)
PMODB4_N: R111.2 U2.D16 | length 3040.6
  Component Side w5: U2.D16@4092.17,3484.28 4093.72,3484.28 v1(4110,3468) ; v3(6195,4933) 6195,4958.49 R111.2@6197.71,4961.2
  GND/Signal w6: v1(4110,3468) 4122.5,3455.5 4135.38,3455.5 4146.12,3444.76 4199.76,3444.76 4246,3491 4286,3491 4349,3554 4571,3554 4728,3711 4728,4053 4836,4161 5551.53,4161 6188.14,4797.62 6188.14,4925.71 6195,4932.57 v3(6195,4933)
PMODB4_P: R109.2 U2.E16 | length 3129.1
  Component Side w5: U2.E16@4092.17,3444.91 4096.09,3444.91 v1(4111,3430) ; v3(6165.57,4932.57) R109.2@6165.57,4961.2
  GND/Signal w6: v1(4111,3430) 4123.5,3442.5 4130,3442.5 4140.74,3431.76 4205.15,3431.76 4251.38,3478 4291.38,3478 4354.38,3541 4576.38,3541 4737.19,3701.81 4741,3705.62 4741,4047.62 4841.38,4148 5556.91,4148 6201.14,4792.23 6201.14,4914.14 6212,4925 6212,4943.04 6205.04,4950 6187.96,4950 6170.53,4932.57 v3(6165.57,4932.57)
PRESNT_M2C: R96.2 U2.T21 | length 267.4
  Component Side w6: U2.T21@4289.02,3011.83 4297.21,3020.03 v1(4304.54,3020.03)
  Bottom Side w6.61: v1(4304.54,3020.03) 4304.54,3023.54 4306.3,3021.79 4315.84,3012.25 4323.69,3012.25 4350.94,2985 4452.01,2985 4500,2937.01 R96.2@4500,2923.31
PRESNT_M2C_L: J1.H2 R18.1 R96.1 | length 3440.9
  Component Side w6.61: J1.H2@6597.44,2437.2 6623.8,2437.2 v3(6625,2436)
  Bottom Side w6.61: R96.1@4500,2888.78 R18.1@4531.5,2888.78 ; R18.1@4531.5,2888.27 4557.56,2888.27 v2(4559.06,2889.76) 4559.06,2877.06 4540,2858 4432,2858 4360,2786 4345,2786 4309,2822 4159,2822 4147,2810 4147,2718 4211,2654 5560,2654 5713,2501 6328,2501 6362,2535 6473,2535 6560,2622 6582,2622 6596.87,2607.13 6596.87,2607 6598,2605.87 6598,2471 6622,2447 6622,2439 v3(6625,2436)
QSPI_CS: R7.1 U1.7 U2.T19 | length 1263.4
  Component Side w6: U2.T19@4210.28,3011.83 4230.11,2992 4353,2992 4380.43,2964.57 5131.17,2964.57 v2(5140.47,2973.87)
  Bottom Side w8: v2(5140.47,2973.87) 5272.35,3105.75 R7.1@5272.35,3157.47
  Bottom Side w20: U1.7@5200.82,3157.47 R7.1@5272.35,3157.47
QSPI_IO0: U1.15 U2.P22 | length 917.7
  Component Side w6: U2.P22@4328.39,3090.57 4329.46,3089.5 4837.53,3089.5 4878,3129.97 v2(4878,3390)
  Bottom Side w8: U1.15@4793,3404 4807,3390 v2(4878,3390)
QSPI_IO1: U1.8 U2.R22 | length 891.1
  Component Side w6: U2.R22@4328.39,3051.2 4585.8,3051.2 4593.69,3043.31 5071.31,3043.31 v2(5131,3103)
  Bottom Side w8: v2(5131,3103) U1.8@5191.51,3103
